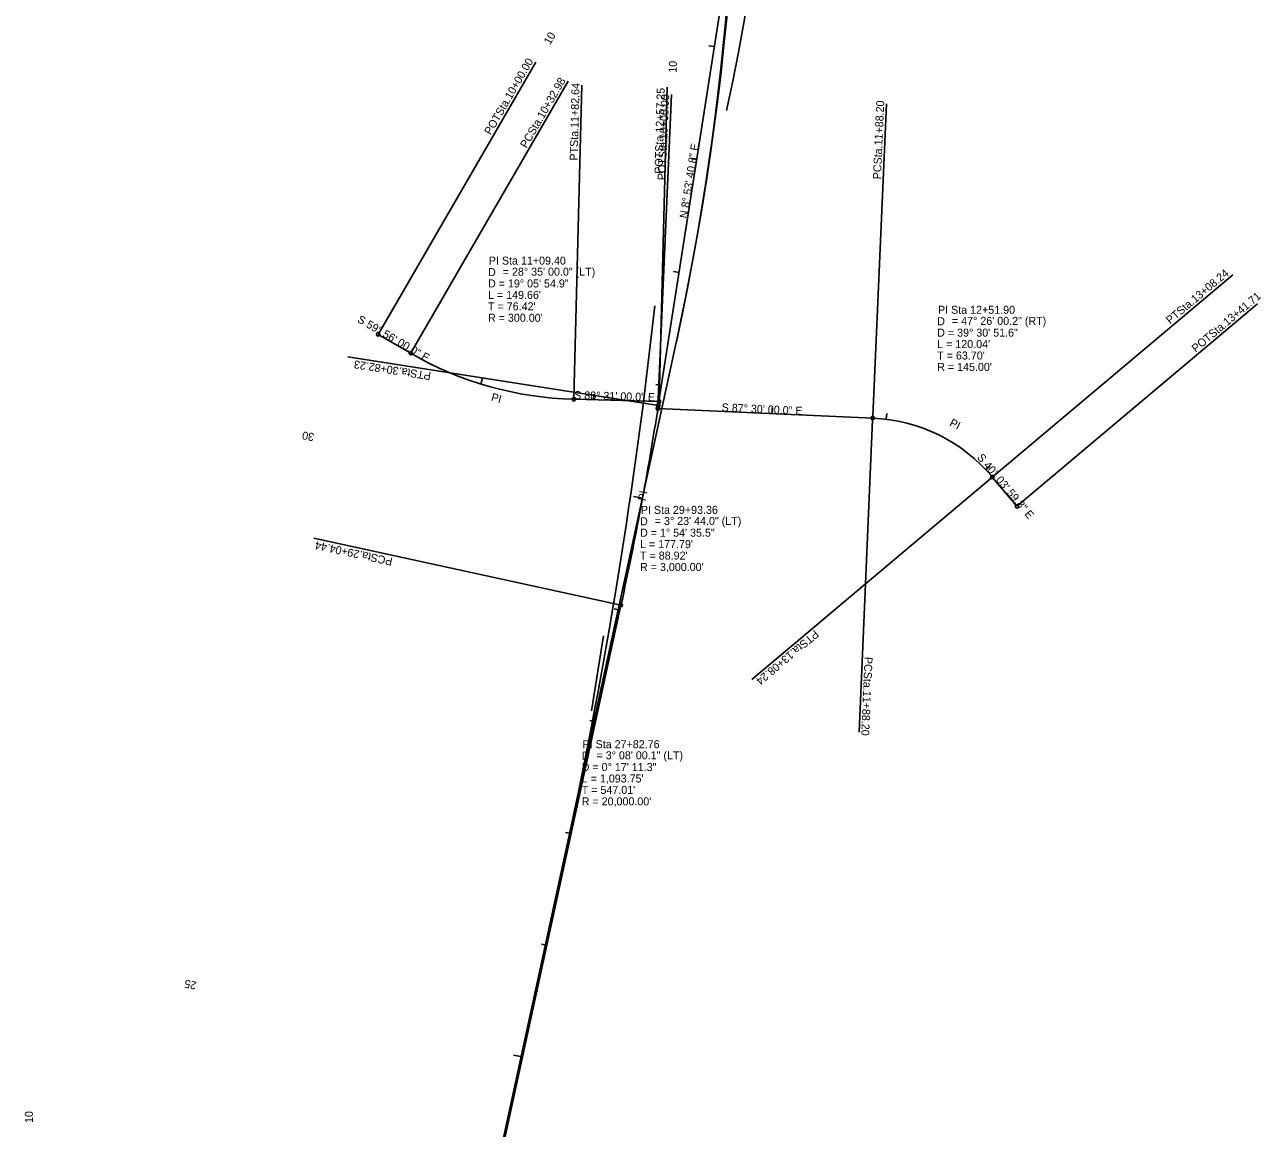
# Model space of a CAD drawing. Extents: x 1615740 to 1617154, y 899624 to 904812.
# Drawn here: x 1616072 to 1617154, y 901029 to 901994 of the extents above; entities that cross this region are included whole.
import ezdxf

# ---------------------------------------------------------------- set-up
doc = ezdxf.new("R2010")
doc.units = 0
for name, color, linetype in [('Default', 7, 'Continuous'), ('Exist Plan Preparation Drainage Flow Arrows', 7, 'Continuous'), ('Exist Plan Preparation Drainage Notes Label', 7, 'Continuous'), ('Exist Structure Minor Pipes CMP 15 Inch Text', 7, 'Continuous'), ('Exist Structure Minor Pipes CMP 24 Inch Text', 7, 'Continuous'), ('Exist Structure Minor Pipes RCP 12 Inch Text', 7, 'Continuous'), ('Exist Structure Minor Pipes RCP 24 Inch Text', 7, 'Continuous'), ('Prop Plan Preparation Sag', 7, 'Continuous'), ('Scratch_Level_7', 7, 'Continuous')]:
    doc.layers.add(name, color=color, linetype=linetype)

msp = doc.modelspace()

# ---------------------------------------------------------------- linework, layer by layer
at = {"layer": 'Default'}
for p, q in [((1616230.1, 899820.8), (1616642, 901715.9)), ((1616187.7, 899625.4), (1616607.2, 901555.9)), ((1616567.9, 901393.7), (1616578.4, 901459.2)), ((1616567.9, 901393.7), (1616578.4, 901459.2)), ((1616187.7, 899625.4), (1616542.1, 901256.2)), ((1616187.7, 899625.4), (1616542.1, 901256.2)), ((1616187.7, 899625.4), (1616542.1, 901256.2)), ((1616187.7, 899625.4), (1616542.1, 901256.2))]:
    msp.add_line(p, q, dxfattribs=at)
for centre, radius, end in [((1614731.7, 902343.6), 2000, 34.8085), ((1614394.4, 902204.1), 2300, 19.583), ((1614394.4, 902204.1), 2300, 19.583), ((1612149.4, 902233.3), 4500, 353.8069)]:
    msp.add_arc(centre, radius, 347.74, end, dxfattribs=at)
at = {"layer": 'Exist Plan Preparation Drainage Flow Arrows'}
for p, q in [((1616381.2, 901723), (1616385.2, 901729.9)), ((1616381.2, 901723), (1616385.2, 901729.9)), ((1616381.2, 901723), (1616385.2, 901729.9)), ((1616381.2, 901723), (1616385.2, 901729.9)), ((1616625.9, 901658), (1616626.2, 901666)), ((1616625.9, 901658), (1616626.2, 901666)), ((1616625.9, 901658), (1616626.2, 901666)), ((1616625.9, 901658), (1616626.2, 901666)), ((1616612.5, 901579.7), (1616604.6, 901581.2)), ((1616612.5, 901579.7), (1616604.6, 901581.2)), ((1616612.5, 901579.7), (1616604.6, 901581.2)), ((1616612.5, 901579.7), (1616604.6, 901581.2)), ((1616507.6, 901090.9), (1616499.7, 901092.6)), ((1616507.6, 901090.9), (1616499.7, 901092.6)), ((1616507.6, 901090.9), (1616499.7, 901092.6)), ((1616507.6, 901090.9), (1616499.7, 901092.6))]:
    msp.add_line(p, q, dxfattribs=at)
at = {"layer": 'Exist Plan Preparation Drainage Notes Label'}
for p, q in [((1616675.5, 901974.7), (1616670.5, 901975.5)), ((1616675.5, 901974.7), (1616670.5, 901975.5)), ((1616675.5, 901974.7), (1616670.5, 901975.5)), ((1616675.5, 901974.7), (1616670.5, 901975.5)), ((1616660, 901875.9), (1616655.1, 901876.7)), ((1616660, 901875.9), (1616655.1, 901876.7)), ((1616660, 901875.9), (1616655.1, 901876.7)), ((1616660, 901875.9), (1616655.1, 901876.7)), ((1616644.5, 901777.1), (1616639.6, 901777.9)), ((1616644.5, 901777.1), (1616639.6, 901777.9)), ((1616644.5, 901777.1), (1616639.6, 901777.9)), ((1616644.5, 901777.1), (1616639.6, 901777.9)), ((1616471, 901679.6), (1616472.5, 901684.4)), ((1616471, 901679.6), (1616472.5, 901684.4)), ((1616471, 901679.6), (1616472.5, 901684.4)), ((1616471, 901679.6), (1616472.5, 901684.4)), ((1616569.6, 901665.7), (1616569.8, 901670.7)), ((1616569.6, 901665.7), (1616569.8, 901670.7)), ((1616569.6, 901665.7), (1616569.8, 901670.7)), ((1616569.6, 901665.7), (1616569.8, 901670.7)), ((1616629.1, 901678.3), (1616624.1, 901679.1)), ((1616629.1, 901678.3), (1616624.1, 901679.1)), ((1616629.1, 901678.3), (1616624.1, 901679.1)), ((1616629.1, 901678.3), (1616624.1, 901679.1)), ((1616725.8, 901653.6), (1616726, 901658.6)), ((1616725.8, 901653.6), (1616726, 901658.6)), ((1616725.8, 901653.6), (1616726, 901658.6)), ((1616725.8, 901653.6), (1616726, 901658.6)), ((1616825.7, 901648.8), (1616826.3, 901653.7)), ((1616825.7, 901648.8), (1616826.3, 901653.7)), ((1616825.7, 901648.8), (1616826.3, 901653.7)), ((1616825.7, 901648.8), (1616826.3, 901653.7)), ((1616913.1, 901604.4), (1616916.7, 901607.8)), ((1616913.1, 901604.4), (1616916.7, 901607.8)), ((1616913.1, 901604.4), (1616916.7, 901607.8)), ((1616913.1, 901604.4), (1616916.7, 901607.8)), ((1616592.7, 901481.7), (1616587.8, 901482.8)), ((1616592.7, 901481.7), (1616587.8, 901482.8)), ((1616592.7, 901481.7), (1616587.8, 901482.8)), ((1616592.7, 901481.7), (1616587.8, 901482.8)), ((1616571.4, 901384), (1616566.5, 901385.1)), ((1616571.4, 901384), (1616566.5, 901385.1)), ((1616571.4, 901384), (1616566.5, 901385.1)), ((1616571.4, 901384), (1616566.5, 901385.1)), ((1616550.1, 901286.3), (1616545.2, 901287.4)), ((1616550.1, 901286.3), (1616545.2, 901287.4)), ((1616550.1, 901286.3), (1616545.2, 901287.4)), ((1616550.1, 901286.3), (1616545.2, 901287.4)), ((1616528.8, 901188.6), (1616524, 901189.7)), ((1616528.8, 901188.6), (1616524, 901189.7)), ((1616528.8, 901188.6), (1616524, 901189.7)), ((1616528.8, 901188.6), (1616524, 901189.7))]:
    msp.add_line(p, q, dxfattribs=at)
at = {"layer": 'Exist Structure Minor Pipes CMP 24 Inch Text'}
for p, q in [((1616626.3, 901660.8), (1616688.4, 902057.6)), ((1616381.2, 901723), (1616409.7, 901706.5)), ((1616552.3, 901666.2), (1616626.9, 901664.3)), ((1616625.9, 901658), (1616813.9, 901649.8)), ((1616918.5, 901598.2), (1616940.1, 901572.6)), ((1616188.3, 899625.3), (1616593.6, 901486.1))]:
    msp.add_line(p, q, dxfattribs=at)
for centre, radius, start, end in [((1616560, 901966.1), 300, 239.9333, 268.5167), ((1613662.4, 902124.6), 3000, 347.7098, 351.1053), ((1616807.6, 901504.9), 145, 40.0666, 87.5)]:
    msp.add_arc(centre, radius, start, end, dxfattribs=at)
at = {"layer": 'Exist Structure Minor Pipes RCP 12 Inch Text'}
msp.add_line((1616230.1, 899820.8), (1616641.9, 901715.8), dxfattribs=at)
msp.add_arc((1614296.8, 902226.1), 2400, 347.74, 24.1286, dxfattribs=at)
at = {"layer": 'Prop Plan Preparation Sag'}
for p, q in [((1616382, 901724.3), (1616519, 901961)), ((1616382, 901724.3), (1616519, 901961)), ((1616382, 901724.3), (1616519, 901961)), ((1616382, 901724.3), (1616519, 901961)), ((1616410.5, 901707.8), (1616547.5, 901944.5)), ((1616410.5, 901707.8), (1616547.5, 901944.5)), ((1616410.5, 901707.8), (1616547.5, 901944.5)), ((1616410.5, 901707.8), (1616547.5, 901944.5)), ((1616552.3, 901667.7), (1616559.4, 901941.1)), ((1616552.3, 901667.7), (1616559.4, 901941.1)), ((1616552.3, 901667.7), (1616559.4, 901941.1)), ((1616552.3, 901667.7), (1616559.4, 901941.1)), ((1616625.9, 901659.5), (1616637.9, 901932.7)), ((1616625.9, 901659.5), (1616637.9, 901932.7)), ((1616625.9, 901659.5), (1616637.9, 901932.7)), ((1616625.9, 901659.5), (1616637.9, 901932.7)), ((1616626.9, 901665.8), (1616634, 901939.2)), ((1616626.9, 901665.8), (1616634, 901939.2)), ((1616626.9, 901665.8), (1616634, 901939.2)), ((1616626.9, 901665.8), (1616634, 901939.2)), ((1616814, 901651.3), (1616825.9, 901924.5)), ((1616919.7, 901599.2), (1617129, 901775.2)), ((1616941.2, 901573.6), (1617150.5, 901749.6)), ((1616941.2, 901573.6), (1617150.5, 901749.6)), ((1616941.2, 901573.6), (1617150.5, 901749.6)), ((1616941.2, 901573.6), (1617150.5, 901749.6)), ((1616624.8, 901661), (1616354.6, 901703.3)), ((1616624.8, 901661), (1616354.6, 901703.3)), ((1616624.8, 901661), (1616354.6, 901703.3)), ((1616624.8, 901661), (1616354.6, 901703.3)), ((1616813.8, 901648.3), (1616801.9, 901375)), ((1616813.8, 901648.3), (1616801.9, 901375)), ((1616813.8, 901648.3), (1616801.9, 901375)), ((1616917.4, 901597.3), (1616708.1, 901421.2)), ((1616917.4, 901597.3), (1616708.1, 901421.2)), ((1616917.4, 901597.3), (1616708.1, 901421.2)), ((1616592.2, 901486.4), (1616324.9, 901544.6)), ((1616592.2, 901486.4), (1616324.9, 901544.6)), ((1616592.2, 901486.4), (1616324.9, 901544.6)), ((1616592.2, 901486.4), (1616324.9, 901544.6))]:
    msp.add_line(p, q, dxfattribs=at)
for centre in [(1616381.2, 901723), (1616381.2, 901723), (1616381.2, 901723), (1616381.2, 901723), (1616409.7, 901706.5), (1616409.7, 901706.5), (1616409.7, 901706.5), (1616409.7, 901706.5), (1616552.3, 901666.2), (1616552.3, 901666.2), (1616552.3, 901666.2), (1616552.3, 901666.2), (1616625.9, 901658), (1616625.9, 901658), (1616625.9, 901658), (1616625.9, 901658), (1616626.3, 901660.8), (1616626.3, 901660.8), (1616626.3, 901660.8), (1616626.3, 901660.8), (1616626.9, 901664.3), (1616626.9, 901664.3), (1616626.9, 901664.3), (1616626.9, 901664.3), (1616813.9, 901649.8), (1616813.9, 901649.8), (1616813.9, 901649.8), (1616813.9, 901649.8), (1616918.5, 901598.2), (1616918.5, 901598.2), (1616918.5, 901598.2), (1616918.5, 901598.2), (1616940.1, 901572.6), (1616940.1, 901572.6), (1616940.1, 901572.6), (1616940.1, 901572.6), (1616593.6, 901486.1), (1616593.6, 901486.1), (1616593.6, 901486.1), (1616593.6, 901486.1)]:
    msp.add_circle(centre, 1.5, dxfattribs=at)

# ---------------------------------------------------------------- texts
at = {"layer": 'Default'}
for rotation, p in [(344.225, (1616479.5, 901665.1)), (344.225, (1616479.5, 901665.1)), (333.7833, (1616880.5, 901643.3)), (333.7833, (1616880.5, 901643.3)), (79.4076, (1616615.3, 901576.8)), (79.4076, (1616615.3, 901576.8))]:
    msp.add_text('PI ', height=7, rotation=rotation, dxfattribs=at).set_placement(p)
at = {"layer": 'Exist Structure Minor Pipes CMP 15 Inch Text'}
for s, rotation, p in [('N 8%%d 53\' 40.8" E', 81.1053, (1616651.7, 901824.1)), ('N 8%%d 53\' 40.8" E', 81.1053, (1616651.7, 901824.1)), ('N 8%%d 53\' 40.8" E', 81.1053, (1616651.7, 901824.1)), ('N 8%%d 53\' 40.8" E', 81.1053, (1616651.7, 901824.1)), ('S 59%%d 56\' 00.0" E', 329.9333, (1616362.4, 901734.1)), ('S 59%%d 56\' 00.0" E', 329.9333, (1616362.4, 901734.1)), ('S 88%%d 31\' 00.0" E', 358.5167, (1616552.6, 901666.4)), ('S 88%%d 31\' 00.0" E', 358.5167, (1616552.6, 901666.4)), ('S 87%%d 30\' 00.0" E', 357.5, (1616681.6, 901655.7)), ('S 87%%d 30\' 00.0" E', 357.5, (1616681.6, 901655.7)), ('S 40%%d 03\' 59.8" E', 310.0666, (1616904.7, 901615)), ('S 40%%d 03\' 59.8" E', 310.0666, (1616904.7, 901615))]:
    msp.add_text(s, height=7, rotation=rotation, dxfattribs=at).set_placement(p)
at = {"layer": 'Exist Structure Minor Pipes RCP 24 Inch Text'}
for s, p in [('PI Sta 11+09.40', (1616478, 901784)), ('PI Sta 11+09.40', (1616478, 901784)), ('D', (1616477.3, 901774)), ('D', (1616477.3, 901774)), ('= 28%%d 35\' 00.0" (LT)', (1616490.2, 901774.3)), ('= 28%%d 35\' 00.0" (LT)', (1616490.2, 901774.3)), ('D = 19%%d 05\' 54.9"', (1616477.3, 901764)), ('D = 19%%d 05\' 54.9"', (1616477.3, 901764)), ("L = 149.66'", (1616477.3, 901754)), ("L = 149.66'", (1616477.3, 901754)), ("T = 76.42'", (1616477.3, 901744)), ("T = 76.42'", (1616477.3, 901744)), ('PI Sta 12+51.90', (1616871, 901741)), ('PI Sta 12+51.90', (1616871, 901741)), ("R = 300.00'", (1616477.3, 901734)), ("R = 300.00'", (1616477.3, 901734)), ('D', (1616870.3, 901731)), ('D', (1616870.3, 901731)), ('= 47%%d 26\' 00.2" (RT)', (1616883.2, 901731.3)), ('= 47%%d 26\' 00.2" (RT)', (1616883.2, 901731.3)), ('D = 39%%d 30\' 51.6"', (1616870.3, 901721)), ('D = 39%%d 30\' 51.6"', (1616870.3, 901721)), ("L = 120.04'", (1616870.3, 901711)), ("L = 120.04'", (1616870.3, 901711)), ("T = 63.70'", (1616870.3, 901701)), ("T = 63.70'", (1616870.3, 901701)), ("R = 145.00'", (1616870.3, 901691)), ("R = 145.00'", (1616870.3, 901691)), ('PI Sta 29+93.36', (1616611, 901566)), ('PI Sta 29+93.36', (1616611, 901566)), ('PI Sta 29+93.36', (1616611, 901566)), ('PI Sta 29+93.36', (1616611, 901566)), ('D', (1616610.3, 901556)), ('D', (1616610.3, 901556)), ('D', (1616610.3, 901556)), ('D', (1616610.3, 901556)), ('= 3%%d 23\' 44.0" (LT)', (1616623.2, 901556.3)), ('= 3%%d 23\' 44.0" (LT)', (1616623.2, 901556.3)), ('= 3%%d 23\' 44.0" (LT)', (1616623.2, 901556.3)), ('= 3%%d 23\' 44.0" (LT)', (1616623.2, 901556.3)), ('D = 1%%d 54\' 35.5"', (1616610.3, 901546)), ('D = 1%%d 54\' 35.5"', (1616610.3, 901546)), ('D = 1%%d 54\' 35.5"', (1616610.3, 901546)), ('D = 1%%d 54\' 35.5"', (1616610.3, 901546)), ("L = 177.79'", (1616610.3, 901536)), ("L = 177.79'", (1616610.3, 901536)), ("L = 177.79'", (1616610.3, 901536)), ("L = 177.79'", (1616610.3, 901536)), ("T = 88.92'", (1616610.3, 901526)), ("T = 88.92'", (1616610.3, 901526)), ("T = 88.92'", (1616610.3, 901526)), ("T = 88.92'", (1616610.3, 901526)), ("R = 3,000.00'", (1616610.3, 901516)), ("R = 3,000.00'", (1616610.3, 901516)), ("R = 3,000.00'", (1616610.3, 901516)), ("R = 3,000.00'", (1616610.3, 901516)), ('PI Sta 27+82.76', (1616560, 901361)), ('PI Sta 27+82.76', (1616560, 901361)), ('D', (1616559.3, 901351)), ('D', (1616559.3, 901351)), ('= 3%%d 08\' 00.1" (LT)', (1616572.2, 901351.3)), ('= 3%%d 08\' 00.1" (LT)', (1616572.2, 901351.3)), ('D = 0%%d 17\' 11.3"', (1616559.3, 901341)), ('D = 0%%d 17\' 11.3"', (1616559.3, 901341)), ("L = 1,093.75'", (1616559.3, 901331)), ("L = 1,093.75'", (1616559.3, 901331)), ("T = 547.01'", (1616559.3, 901321)), ("T = 547.01'", (1616559.3, 901321)), ("R = 20,000.00'", (1616559.3, 901311)), ("R = 20,000.00'", (1616559.3, 901311))]:
    msp.add_text(s, height=7, dxfattribs=at).set_placement(p)
at = {"layer": 'Prop Plan Preparation Sag'}
for s, rotation, p in [('POTSta.10+00.00', 59.9333, (1616479.6, 901896.9)), ('POTSta.10+00.00', 59.9333, (1616479.6, 901896.9)), ('POTSta.10+00.00', 59.9333, (1616479.6, 901896.9)), ('POTSta.10+00.00', 59.9333, (1616479.6, 901896.9)), ('PCSta.10+32.98', 59.9333, (1616511, 901885.3)), ('PCSta.10+32.98', 59.9333, (1616511, 901885.3)), ('PCSta.10+32.98', 59.9333, (1616511, 901885.3)), ('PCSta.10+32.98', 59.9333, (1616511, 901885.3)), ('PTSta.11+82.64', 88.5167, (1616555.7, 901874.9)), ('PTSta.11+82.64', 88.5167, (1616555.7, 901874.9)), ('PTSta.11+82.64', 88.5167, (1616555.7, 901874.9)), ('PTSta.11+82.64', 88.5167, (1616555.7, 901874.9)), ('POTSta.12+57.25', 88.5167, (1616630, 901863.4)), ('POTSta.12+57.25', 88.5167, (1616630, 901863.4)), ('POTSta.12+57.25', 88.5167, (1616630, 901863.4)), ('POTSta.12+57.25', 88.5167, (1616630, 901863.4)), ('POTSta.10+00.00', 87.5, (1616632.6, 901857.7)), ('POTSta.10+00.00', 87.5, (1616632.6, 901857.7)), ('POTSta.10+00.00', 87.5, (1616632.6, 901857.7)), ('POTSta.10+00.00', 87.5, (1616632.6, 901857.7)), ('PCSta.11+88.20', 87.5, (1616821, 901858.5)), ('PTSta.13+08.24', 40.0666, (1617074.1, 901731.6)), ('POTSta.13+41.71', 40.0666, (1617096.6, 901706.9)), ('POTSta.13+41.71', 40.0666, (1617096.6, 901706.9)), ('POTSta.13+41.71', 40.0666, (1617096.6, 901706.9)), ('POTSta.13+41.71', 40.0666, (1617096.6, 901706.9)), ('PTSta.30+82.23', 171.1053, (1616427.8, 901689.8)), ('PTSta.30+82.23', 171.1053, (1616427.8, 901689.8)), ('PTSta.30+82.23', 171.1053, (1616427.8, 901689.8)), ('PTSta.30+82.23', 171.1053, (1616427.8, 901689.8)), ('PCSta.29+04.44', 167.7098, (1616394.3, 901527.4)), ('PCSta.29+04.44', 167.7098, (1616394.3, 901527.4)), ('PCSta.29+04.44', 167.7098, (1616394.3, 901527.4)), ('PCSta.29+04.44', 167.7098, (1616394.3, 901527.4)), ('PTSta.13+08.24', 220.0666, (1616763, 901464.8)), ('PTSta.13+08.24', 220.0666, (1616763, 901464.8)), ('PTSta.13+08.24', 220.0666, (1616763, 901464.8)), ('PCSta.11+88.20', 267.5, (1616806.8, 901441)), ('PCSta.11+88.20', 267.5, (1616806.8, 901441)), ('PCSta.11+88.20', 267.5, (1616806.8, 901441))]:
    msp.add_text(s, height=7, rotation=rotation, dxfattribs=at).set_placement(p)
at = {"layer": 'Scratch_Level_7'}
for s, rotation, p in [('10', 59.9333, (1616531.6, 901975.8)), ('10', 59.9333, (1616531.6, 901975.8)), ('10', 59.9333, (1616531.6, 901975.8)), ('10', 59.9333, (1616531.6, 901975.8)), ('10', 87.5, (1616642.2, 901951.7)), ('10', 87.5, (1616642.2, 901951.7)), ('10', 87.5, (1616642.2, 901951.7)), ('10', 87.5, (1616642.2, 901951.7)), ('30', 169.5348, (1616325.7, 901636.3)), ('30', 169.5348, (1616325.7, 901636.3)), ('30', 169.5348, (1616325.7, 901636.3)), ('30', 169.5348, (1616325.7, 901636.3)), ('25', 167.7098, (1616222.7, 901156.5)), ('25', 167.7098, (1616222.7, 901156.5)), ('25', 167.7098, (1616222.7, 901156.5)), ('25', 167.7098, (1616222.7, 901156.5)), ('10', 90.894, (1616079.2, 901033.2)), ('10', 90.894, (1616079.2, 901033.2)), ('10', 90.894, (1616079.2, 901033.2)), ('10', 90.894, (1616079.2, 901033.2))]:
    msp.add_text(s, height=7, rotation=rotation, dxfattribs=at).set_placement(p)

doc.saveas('drawing.dxf')
